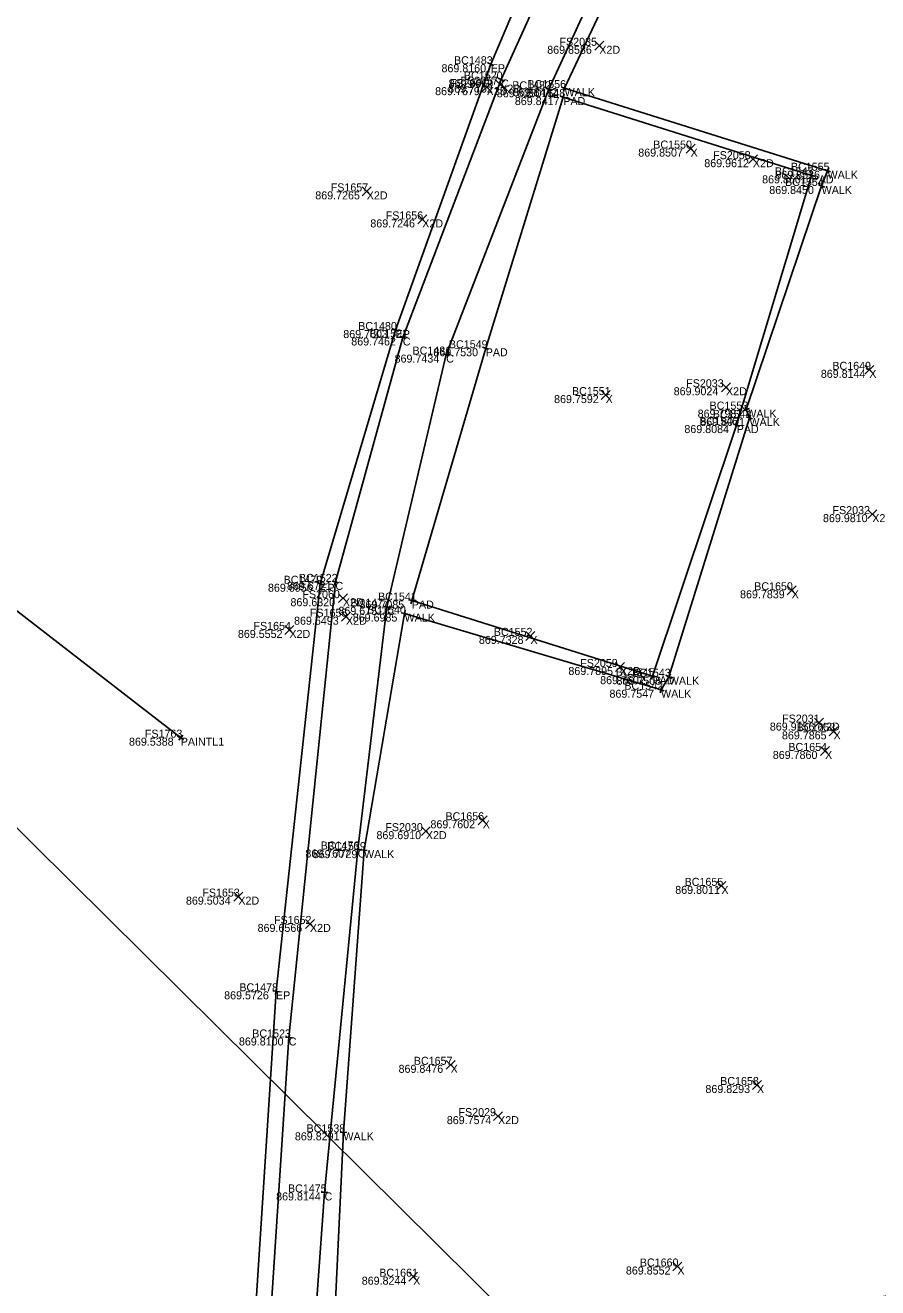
# Model space of a CAD drawing. Extents: x 1479425 to 1480294, y 379351 to 380102.
# Drawn here: x 1479693.48 to 1479699.88, y 379912.39 to 379921.85 of the extents above; entities that cross this region are included whole.
import ezdxf

# ---------------------------------------------------------------- set-up
doc = ezdxf.new("R2010")
doc.units = 0
for name, color, linetype in [('PM_X_Crosswalk', 7, 'Continuous'), ('PV_X_Curb', 7, 'Continuous'), ('PV_X_Walk', 7, 'Continuous'), ('RD_X_Concrete_Pad', 7, 'Continuous'), ('SV_X_Random_Point', 7, 'Continuous'), ('SV_X_Shot_Marker', 7, 'Continuous'), ('SV_X_Text_Comment', 7, 'Continuous'), ('SV_X_Text_Elevation', 7, 'Continuous'), ('SV_X_Text_Name', 7, 'Continuous'), ('UT_X_Gas', 7, 'Continuous')]:
    doc.layers.add(name, color=color, linetype=linetype)

msp = doc.modelspace()

# ---------------------------------------------------------------- linework, layer by layer
at = {"layer": 'PM_X_Crosswalk'}
msp.add_lwpolyline([(1479663.295, 379940.7859), (1479694.651, 379916.5128)], dxfattribs=at)
at = {"layer": 'PV_X_Curb'}
for points in [[(1479696.2636, 379903.5386), (1479695.5705, 379906.7461), (1479695.2973, 379909.3412), (1479695.1738, 379911.6458), (1479695.3654, 379914.6115), (1479695.6976, 379917.6668), (1479696.2624, 379919.5688), (1479696.9758, 379921.5611), (1479698.1082, 379924.2136), (1479700.2799, 379927.5011), (1479703.0248, 379930.6372), (1479705.9498, 379933.539), (1479706.9435, 379934.3789), (1479708.0749, 379934.8076), (1479711.183, 379937.5526), (1479719.99, 379942.1167), (1479736.739, 379950.5318), (1479753.296, 379958.795), (1479766.716, 379965.5627), (1479785.836, 379974.8289), (1479802.25, 379983.0541), (1479831.407, 379997.252)], [(1479714.5618, 379931.5973), (1479714.9536, 379931.8464), (1479713.9233, 379933.1457), (1479712.2808, 379934.1691), (1479710.4236, 379934.7733), (1479708.7692, 379934.7899), (1479708.1103, 379934.7976), (1479707.0655, 379934.2154), (1479706.4002, 379933.8431), (1479705.6821, 379933.0592), (1479703.0049, 379930.3348), (1479700.4209, 379927.5017), (1479698.1162, 379923.7926), (1479697.0539, 379921.4468), (1479696.3167, 379919.5129), (1479695.8109, 379917.6805), (1479695.4613, 379914.2655), (1479695.2919, 379911.6604), (1479695.2827, 379911.4711), (1479695.5098, 379908.7638), (1479695.6518, 379906.8062)], [(1479696.7341, 379903.7226), (1479696.0777, 379906.871), (1479695.8572, 379909.3669), (1479695.6789, 379911.5748), (1479695.6301, 379911.7177), (1479695.7295, 379913.104), (1479695.9783, 379915.6746), (1479696.1977, 379917.4938), (1479696.6417, 379919.3847), (1479697.4123, 379921.3734), (1479698.5912, 379923.9386), (1479699.838, 379926.0575), (1479700.67, 379927.1843), (1479703.3721, 379930.2685), (1479706.2512, 379933.0593), (1479706.6718, 379933.5352), (1479707.0448, 379933.7387), (1479707.4133, 379933.9238), (1479708.304, 379934.3327), (1479710.1486, 379934.3742), (1479711.6155, 379933.9308), (1479713.6212, 379932.8847), (1479714.2993, 379932.0346), (1479714.5618, 379931.5973)]]:
    msp.add_lwpolyline(points, dxfattribs=at)
at = {"layer": 'PV_X_Walk'}
msp.add_lwpolyline([(1479701.8352, 379912.4997), (1479701.2507, 379912.5611), (1479699.8235, 379912.3065), (1479697.4959, 379911.9204), (1479695.7834, 379911.7114), (1479695.8711, 379913.5546), (1479696.0253, 379915.6699), (1479696.3297, 379917.4434), (1479698.2528, 379916.8723), (1479698.3113, 379916.9697), (1479698.9161, 379918.9097), (1479698.892, 379918.9723), (1479699.4573, 379920.6485), (1479699.5018, 379920.7626), (1479697.5293, 379921.3818), (1479698.4277, 379923.2922)], dxfattribs=at)
at = {"layer": 'RD_X_Concrete_Pad'}
msp.add_lwpolyline([(1479696.3836, 379917.5408), (1479698.1885, 379916.9739), (1479698.8201, 379918.8561), (1479699.3822, 379920.7281), (1479697.5202, 379921.3149), (1479696.938, 379919.4321)], close=True, dxfattribs=at)
at = {"layer": 'SV_X_Random_Point'}
for p, q in [((1479697.7567, 379921.6661), (1479697.8233, 379921.7329)), ((1479697.7567, 379921.7329), (1479697.8233, 379921.6661)), ((1479697.0137, 379921.3747), (1479697.0803, 379921.4415)), ((1479697.0137, 379921.4415), (1479697.0803, 379921.3747)), ((1479696.9117, 379921.356), (1479696.9783, 379921.4228)), ((1479696.9117, 379921.4228), (1479696.9783, 379921.356)), ((1479698.4416, 379920.8955), (1479698.5082, 379920.9623)), ((1479698.4416, 379920.9623), (1479698.5082, 379920.8955)), ((1479698.9087, 379920.8161), (1479698.9753, 379920.8829)), ((1479698.9087, 379920.8829), (1479698.9753, 379920.8161)), ((1479696.0127, 379920.5747), (1479696.0793, 379920.6415)), ((1479696.0127, 379920.6415), (1479696.0793, 379920.5747)), ((1479696.4287, 379920.3644), (1479696.4953, 379920.4312)), ((1479696.4287, 379920.4312), (1479696.4953, 379920.3644)), ((1479699.7814, 379919.2369), (1479699.848, 379919.3037)), ((1479699.7814, 379919.3037), (1479699.848, 379919.2369)), ((1479698.7067, 379919.1063), (1479698.7733, 379919.1731)), ((1479698.7067, 379919.1731), (1479698.7733, 379919.1063)), ((1479697.804, 379919.0477), (1479697.8706, 379919.1145)), ((1479697.804, 379919.1145), (1479697.8706, 379919.0477)), ((1479699.8037, 379918.1552), (1479699.8703, 379918.222)), ((1479699.8037, 379918.222), (1479699.8703, 379918.1552)), ((1479699.1997, 379917.5845), (1479699.2663, 379917.6513)), ((1479699.1997, 379917.6513), (1479699.2663, 379917.5845)), ((1479695.8337, 379917.525), (1479695.9003, 379917.5918)), ((1479695.8337, 379917.5918), (1479695.9003, 379917.525)), ((1479695.8567, 379917.3861), (1479695.9233, 379917.4529)), ((1479695.8567, 379917.4529), (1479695.9233, 379917.3861)), ((1479695.4327, 379917.2873), (1479695.4993, 379917.3541)), ((1479695.4327, 379917.3541), (1479695.4993, 379917.2873)), ((1479697.24, 379917.2425), (1479697.3066, 379917.3093)), ((1479697.24, 379917.3093), (1479697.3066, 379917.2425)), ((1479697.9117, 379917.0094), (1479697.9783, 379917.0762)), ((1479697.9117, 379917.0762), (1479697.9783, 379917.0094)), ((1479699.4037, 379916.5925), (1479699.4703, 379916.6593)), ((1479699.4037, 379916.6593), (1479699.4703, 379916.5925)), ((1479699.5133, 379916.527), (1479699.5799, 379916.5938)), ((1479699.5133, 379916.5938), (1479699.5799, 379916.527)), ((1479699.45, 379916.38), (1479699.5166, 379916.4468)), ((1479699.45, 379916.4468), (1479699.5166, 379916.38)), ((1479696.8824, 379915.8604), (1479696.949, 379915.9272)), ((1479696.8824, 379915.9272), (1479696.949, 379915.8604)), ((1479696.4557, 379915.7788), (1479696.5223, 379915.8456)), ((1479696.4557, 379915.8456), (1479696.5223, 379915.7788)), ((1479698.6725, 379915.3686), (1479698.7391, 379915.4354)), ((1479698.6725, 379915.4354), (1479698.7391, 379915.3686)), ((1479695.0497, 379915.288), (1479695.1163, 379915.3548)), ((1479695.0497, 379915.3548), (1479695.1163, 379915.288)), ((1479695.5867, 379915.0834), (1479695.6533, 379915.1502)), ((1479695.5867, 379915.1502), (1479695.6533, 379915.0834)), ((1479696.6415, 379914.0271), (1479696.7081, 379914.0939)), ((1479696.6415, 379914.0939), (1479696.7081, 379914.0271)), ((1479698.9395, 379913.8757), (1479699.0061, 379913.9425)), ((1479698.9395, 379913.9425), (1479699.0061, 379913.8757)), ((1479696.9977, 379913.6425), (1479697.0643, 379913.7093)), ((1479696.9977, 379913.7093), (1479697.0643, 379913.6425)), ((1479698.3425, 379912.5152), (1479698.4091, 379912.582)), ((1479698.3425, 379912.582), (1479698.4091, 379912.5152)), ((1479696.361, 379912.4387), (1479696.4276, 379912.5055)), ((1479696.361, 379912.5055), (1479696.4276, 379912.4387))]:
    msp.add_line(p, q, dxfattribs=at)
at = {"layer": 'SV_X_Shot_Marker'}
for p, q in [((1479696.9528, 379921.5709), (1479696.9988, 379921.5513)), ((1479696.966, 379921.5381), (1479696.9856, 379921.5841)), ((1479696.9758, 379921.5611), (1479696.9758, 379921.5611)), ((1479697.0767, 379921.4365), (1479697.0311, 379921.4571)), ((1479697.0642, 379921.4696), (1479697.0436, 379921.424)), ((1479697.0539, 379921.4468), (1479697.0539, 379921.4468)), ((1479697.389, 379921.3825), (1479697.4356, 379921.3644)), ((1479697.4033, 379921.3501), (1479697.4213, 379921.3967)), ((1479697.4123, 379921.3734), (1479697.4123, 379921.3734)), ((1479697.5531, 379921.3743), (1479697.5054, 379921.3893)), ((1479697.5218, 379921.358), (1479697.5368, 379921.4057)), ((1479697.5293, 379921.3818), (1479697.5293, 379921.3818)), ((1479697.544, 379921.3074), (1479697.4964, 379921.3224)), ((1479697.5127, 379921.2911), (1479697.5277, 379921.3388)), ((1479697.5202, 379921.3149), (1479697.5202, 379921.3149)), ((1479699.4927, 379920.7393), (1479699.5109, 379920.7859)), ((1479699.3583, 379920.7353), (1479699.4061, 379920.7209)), ((1479699.375, 379920.7042), (1479699.3894, 379920.7521)), ((1479699.3822, 379920.7281), (1479699.3822, 379920.7281)), ((1479699.4785, 379920.7717), (1479699.5251, 379920.7535)), ((1479699.5018, 379920.7626), (1479699.5018, 379920.7626)), ((1479699.4336, 379920.6565), (1479699.481, 379920.6405)), ((1479699.4493, 379920.6248), (1479699.4653, 379920.6722)), ((1479699.4573, 379920.6485), (1479699.4573, 379920.6485)), ((1479696.2389, 379919.5772), (1479696.2859, 379919.5604)), ((1479696.254, 379919.5453), (1479696.2708, 379919.5924)), ((1479696.2624, 379919.5688), (1479696.2624, 379919.5688)), ((1479696.3401, 379919.504), (1479696.2933, 379919.5218)), ((1479696.3256, 379919.5363), (1479696.3078, 379919.4896)), ((1479696.3167, 379919.5129), (1479696.3167, 379919.5129)), ((1479696.9454, 379919.456), (1479696.9306, 379919.4082)), ((1479696.6174, 379919.3904), (1479696.666, 379919.379)), ((1479696.636, 379919.3604), (1479696.6474, 379919.4091)), ((1479696.6417, 379919.3847), (1479696.6417, 379919.3847)), ((1479696.9619, 379919.4247), (1479696.9141, 379919.4395)), ((1479696.938, 379919.4321), (1479696.938, 379919.4321)), ((1479698.8687, 379918.9633), (1479698.9153, 379918.9813)), ((1479698.901, 379918.949), (1479698.883, 379918.9957)), ((1479698.892, 379918.9723), (1479698.892, 379918.9723)), ((1479698.8922, 379918.9172), (1479698.94, 379918.9023)), ((1479698.9087, 379918.8859), (1479698.9235, 379918.9336)), ((1479698.9161, 379918.9097), (1479698.9161, 379918.9097)), ((1479698.7964, 379918.8641), (1479698.8438, 379918.8482)), ((1479698.8121, 379918.8324), (1479698.828, 379918.8798)), ((1479698.8201, 379918.8561), (1479698.8201, 379918.8561)), ((1479695.6736, 379917.6739), (1479695.7216, 379917.6597)), ((1479695.6905, 379917.6429), (1479695.7047, 379917.6908)), ((1479695.6976, 379917.6668), (1479695.6976, 379917.6668)), ((1479695.835, 379917.6739), (1479695.7868, 379917.6872)), ((1479695.8175, 379917.7046), (1479695.8042, 379917.6564)), ((1479695.8109, 379917.6805), (1479695.8109, 379917.6805)), ((1479696.3911, 379917.5647), (1479696.3761, 379917.517)), ((1479696.1729, 379917.4968), (1479696.2225, 379917.4908)), ((1479696.1947, 379917.469), (1479696.2007, 379917.5186)), ((1479696.1977, 379917.4938), (1479696.1977, 379917.4938)), ((1479696.3255, 379917.4188), (1479696.3339, 379917.4681)), ((1479696.3597, 379917.5483), (1479696.4074, 379917.5333)), ((1479696.3836, 379917.5408), (1479696.3836, 379917.5408)), ((1479696.3051, 379917.4476), (1479696.3543, 379917.4392)), ((1479696.3297, 379917.4434), (1479696.3297, 379917.4434)), ((1479698.196, 379916.9978), (1479698.181, 379916.9501)), ((1479698.2984, 379916.9483), (1479698.3242, 379916.9912)), ((1479698.1646, 379916.9814), (1479698.2123, 379916.9664)), ((1479698.1885, 379916.9739), (1479698.1885, 379916.9739)), ((1479698.2599, 379916.8963), (1479698.2457, 379916.8484)), ((1479698.2899, 379916.9826), (1479698.3327, 379916.9568)), ((1479698.3113, 379916.9697), (1479698.3113, 379916.9697)), ((1479698.2288, 379916.8794), (1479698.2768, 379916.8652)), ((1479698.2528, 379916.8723), (1479698.2528, 379916.8723)), ((1479694.6312, 379916.5281), (1479694.6708, 379916.4975)), ((1479694.6663, 379916.5326), (1479694.6357, 379916.4931)), ((1479694.651, 379916.5128), (1479694.651, 379916.5128)), ((1479695.9534, 379915.677), (1479696.0032, 379915.6722)), ((1479695.9759, 379915.6497), (1479695.9807, 379915.6995)), ((1479695.9783, 379915.6746), (1479695.9783, 379915.6746)), ((1479696.0004, 379915.6717), (1479696.0502, 379915.6681)), ((1479696.0235, 379915.645), (1479696.0271, 379915.6949)), ((1479696.0253, 379915.6699), (1479696.0253, 379915.6699)), ((1479695.3627, 379914.5867), (1479695.3681, 379914.6364)), ((1479695.3405, 379914.6142), (1479695.3903, 379914.6088)), ((1479695.3654, 379914.6115), (1479695.3654, 379914.6115)), ((1479695.4862, 379914.263), (1479695.4364, 379914.2681)), ((1479695.4638, 379914.2904), (1479695.4588, 379914.2406)), ((1479695.4613, 379914.2655), (1479695.4613, 379914.2655)), ((1479695.8461, 379913.5558), (1479695.8961, 379913.5534)), ((1479695.8699, 379913.5296), (1479695.8723, 379913.5796)), ((1479695.8711, 379913.5546), (1479695.8711, 379913.5546)), ((1479695.7277, 379913.0791), (1479695.7313, 379913.129)), ((1479695.7046, 379913.1058), (1479695.7544, 379913.1022)), ((1479695.7295, 379913.104), (1479695.7295, 379913.104))]:
    msp.add_line(p, q, dxfattribs=at)
at = {"layer": 'UT_X_Gas'}
msp.add_lwpolyline([(1479667.444, 379946.5718), (1479666.862, 379942.8024), (1479667.538, 379940.5069), (1479675.403, 379934.5044), (1479682.743, 379926.3262), (1479692.421, 379916.8243), (1479702.659, 379906.6944), (1479713.881, 379895.5671), (1479724.225, 379885.7813), (1479733.117, 379877.7953), (1479742.697, 379869.3255), (1479754.816, 379857.131), (1479762.869, 379849.3179), (1479772.436, 379840.6407), (1479780.346, 379832.7145), (1479784.901, 379828.1912), (1479795.906, 379818.3242), (1479806.128, 379806.7189), (1479816.671, 379794.927)], dxfattribs=at)

# ---------------------------------------------------------------- texts
at = {"layer": 'SV_X_Text_Comment'}
for s, p in [('X2D', (1479697.79, 379921.6395)), ('EP', (1479696.9758, 379921.5011)), ('C', (1479697.0539, 379921.3868)), ('X2D', (1479696.945, 379921.3294)), ('X2D', (1479697.047, 379921.3481)), ('C', (1479697.4123, 379921.3134)), ('WALK', (1479697.5293, 379921.3218)), ('PAD', (1479697.5202, 379921.2549)), ('X', (1479698.4749, 379920.8689)), ('X2D', (1479698.942, 379920.7895)), ('PAD', (1479699.3822, 379920.6681)), ('WALK', (1479699.5018, 379920.7026)), ('X2D', (1479696.046, 379920.5481)), ('WALK', (1479699.4573, 379920.5885)), ('X2D', (1479696.462, 379920.3378)), ('EP', (1479696.2624, 379919.5088)), ('C', (1479696.3167, 379919.4529)), ('C', (1479696.6417, 379919.3247)), ('PAD', (1479696.938, 379919.3721)), ('X', (1479699.8147, 379919.2103)), ('X', (1479697.8373, 379919.0211)), ('X2D', (1479698.74, 379919.0797)), ('WALK', (1479698.892, 379918.9123)), ('WALK', (1479698.9161, 379918.8497)), ('PAD', (1479698.8201, 379918.7961)), ('X2D', (1479699.837, 379918.1286)), ('EP', (1479695.6976, 379917.6068)), ('C', (1479695.8109, 379917.6205)), ('X2D', (1479695.867, 379917.4984)), ('X', (1479699.233, 379917.5579)), ('C', (1479696.1977, 379917.4338)), ('PAD', (1479696.3836, 379917.4808)), ('X2D', (1479695.89, 379917.3595)), ('WALK', (1479696.3297, 379917.3834)), ('X2D', (1479695.466, 379917.2607)), ('X', (1479697.2733, 379917.2159)), ('X2D', (1479697.945, 379916.9828)), ('PAD', (1479698.1885, 379916.9139)), ('WALK', (1479698.3113, 379916.9097)), ('WALK', (1479698.2528, 379916.8123)), ('X2D', (1479699.437, 379916.5659)), ('X', (1479699.5466, 379916.5004)), ('PAINTL1', (1479694.651, 379916.4528)), ('X', (1479699.4833, 379916.3534)), ('X', (1479696.9157, 379915.8338)), ('X2D', (1479696.489, 379915.7522)), ('C', (1479695.9783, 379915.6146)), ('WALK', (1479696.0253, 379915.6099)), ('X', (1479698.7058, 379915.342)), ('X2D', (1479695.083, 379915.2614)), ('X2D', (1479695.62, 379915.0568)), ('EP', (1479695.3654, 379914.5515)), ('C', (1479695.4613, 379914.2055)), ('X', (1479696.6748, 379914.0005)), ('X', (1479698.9728, 379913.8491)), ('X2D', (1479697.031, 379913.6159)), ('WALK', (1479695.8711, 379913.4946)), ('C', (1479695.7295, 379913.044)), ('X', (1479698.3758, 379912.4886)), ('X', (1479696.3943, 379912.4121))]:
    msp.add_text(s, height=0.06, dxfattribs=at).set_placement(p)
at = {"layer": 'SV_X_Text_Elevation'}
for s, p in [('869.8586', (1479697.3993, 379921.6395)), ('869.8160', (1479696.6064, 379921.5011)), ('869.8069', (1479696.6599, 379921.3868)), ('869.7679', (1479696.5586, 379921.3294)), ('869.7702', (1479696.6568, 379921.3481)), ('869.8250', (1479697.0211, 379921.3134)), ('869.8442', (1479697.1419, 379921.3218)), ('869.8417', (1479697.1565, 379921.2549)), ('869.8507', (1479698.0823, 379920.8689)), ('869.9612', (1479698.5773, 379920.7895)), ('869.8601', (1479699.0112, 379920.6681)), ('869.8536', (1479699.1102, 379920.7026)), ('869.7265', (1479695.66, 379920.5481)), ('869.8450', (1479699.0647, 379920.5885)), ('869.7246', (1479696.0727, 379920.3378)), ('869.7603', (1479695.8698, 379919.5088)), ('869.7462', (1479695.9298, 379919.4529)), ('869.7434', (1479696.2548, 379919.3247)), ('869.7530', (1479696.5459, 379919.3721)), ('869.8144', (1479699.4514, 379919.2103)), ('869.7592', (1479697.4509, 379919.0211)), ('869.9024', (1479698.3479, 379919.0797)), ('869.7981', (1479698.5277, 379918.9123)), ('869.8071', (1479698.547, 379918.8497)), ('869.8084', (1479698.428, 379918.7961)), ('869.9810', (1479699.4676, 379918.1286)), ('869.6956', (1479695.305, 379917.6068)), ('869.6721', (1479695.4475, 379917.6205)), ('869.6320', (1479695.4739, 379917.4984)), ('869.7839', (1479698.8456, 379917.5579)), ('869.6751', (1479695.8334, 379917.4338)), ('869.7085', (1479695.992, 379917.4808)), ('869.6493', (1479695.5007, 379917.3595)), ('869.6985', (1479695.9409, 379917.3834)), ('869.5552', (1479695.0796, 379917.2607)), ('869.7328', (1479696.8869, 379917.2159)), ('869.7895', (1479697.5581, 379916.9828)), ('869.7602', (1479697.7964, 379916.9139)), ('869.7508', (1479697.9192, 379916.9097)), ('869.7547', (1479697.8664, 379916.8123)), ('869.9156', (1479699.069, 379916.5659)), ('869.7865', (1479699.1597, 379916.5004)), ('869.5388', (1479694.2627, 379916.4528)), ('869.7860', (1479699.0912, 379916.3534)), ('869.7602', (1479696.5236, 379915.8338)), ('869.6910', (1479696.1187, 379915.7522)), ('869.7607', (1479695.5857, 379915.6146)), ('869.7729', (1479695.6408, 379915.6099)), ('869.8011', (1479698.3594, 379915.342)), ('869.5034', (1479694.6899, 379915.2614)), ('869.6566', (1479695.2274, 379915.0568)), ('869.5726', (1479694.9766, 379914.5515)), ('869.8100', (1479695.0872, 379914.2055)), ('869.8476', (1479696.2846, 379914.0005)), ('869.8293', (1479698.5859, 379913.8491)), ('869.7574', (1479696.6465, 379913.6159)), ('869.8291', (1479695.5068, 379913.4946)), ('869.8144', (1479695.3662, 379913.044)), ('869.8552', (1479697.9894, 379912.4886)), ('869.8244', (1479696.0083, 379912.4121))]:
    msp.add_text(s, height=0.06, dxfattribs=at).set_placement(p)
at = {"layer": 'SV_X_Text_Name'}
for s, p in [('FS2035', (1479697.4914, 379921.6995)), ('BC1483', (1479696.7004, 379921.5611)), ('FS2061', (1479696.669, 379921.3894)), ('FS2057', (1479696.7494, 379921.4081)), ('BC1520', (1479696.7747, 379921.4468)), ('BC1556', (1479697.2506, 379921.3818)), ('BC1482', (1479697.1374, 379921.3734)), ('BC1548', (1479697.2443, 379921.3149)), ('BC1550', (1479698.1948, 379920.9289)), ('FS2058', (1479698.6439, 379920.8495)), ('BC1547', (1479699.1068, 379920.7281)), ('BC1555', (1479699.2269, 379920.7626)), ('BC1554', (1479699.1829, 379920.6485)), ('FS1657', (1479695.7758, 379920.6081)), ('FS1656', (1479696.188, 379920.3978)), ('BC1480', (1479695.9818, 379919.5688)), ('BC1521', (1479696.0653, 379919.5129)), ('BC1549', (1479696.6621, 379919.4321)), ('BC1481', (1479696.3889, 379919.3847)), ('BC1649', (1479699.5379, 379919.2703)), ('FS2033', (1479698.4414, 379919.1397)), ('BC1551', (1479697.5849, 379919.0811)), ('BC1553', (1479698.6171, 379918.9723)), ('BC1546', (1479698.5409, 379918.8561)), ('BC1544', (1479698.6412, 379918.9097)), ('FS2032', (1479699.5389, 379918.1886)), ('BC1479', (1479695.4227, 379917.6668)), ('BC1522', (1479695.5374, 379917.6805)), ('BC1650', (1479698.9519, 379917.6179)), ('FS2060', (1479695.5632, 379917.5584)), ('BC1541', (1479696.1308, 379917.5408)), ('FS1655', (1479695.6198, 379917.4195)), ('BC1477', (1479695.9233, 379917.4938)), ('BC1540', (1479696.0491, 379917.4434)), ('FS1654', (1479695.1963, 379917.3207)), ('BC1552', (1479696.9989, 379917.2759)), ('FS2059', (1479697.6469, 379917.0428)), ('BC1545', (1479697.9131, 379916.9739)), ('BC1543', (1479698.0359, 379916.9697)), ('BC1542', (1479697.9779, 379916.8723)), ('FS2031', (1479699.161, 379916.6259)), ('BC1653', (1479699.2707, 379916.5604)), ('FS1763', (1479694.3818, 379916.5128)), ('BC1654', (1479699.2079, 379916.4134)), ('BC1656', (1479696.6361, 379915.8938)), ('FS2030', (1479696.1852, 379915.8122)), ('BC1476', (1479695.7001, 379915.6746)), ('BC1539', (1479695.749, 379915.6699)), ('FS1653', (1479694.8128, 379915.3214)), ('BC1655', (1479698.4299, 379915.402)), ('FS1652', (1479695.3503, 379915.1168)), ('BC1478', (1479695.0905, 379914.6115)), ('BC1523', (1479695.1873, 379914.2655)), ('BC1657', (1479696.3989, 379914.0605)), ('BC1658', (1479698.6965, 379913.9091)), ('FS2029', (1479696.7339, 379913.6759)), ('BC1538', (1479695.5948, 379913.5546)), ('BC1475', (1479695.4551, 379913.104)), ('BC1660', (1479698.0938, 379912.5486)), ('BC1661', (1479696.1401, 379912.4721))]:
    msp.add_text(s, height=0.06, dxfattribs=at).set_placement(p)

doc.saveas('drawing.dxf')
